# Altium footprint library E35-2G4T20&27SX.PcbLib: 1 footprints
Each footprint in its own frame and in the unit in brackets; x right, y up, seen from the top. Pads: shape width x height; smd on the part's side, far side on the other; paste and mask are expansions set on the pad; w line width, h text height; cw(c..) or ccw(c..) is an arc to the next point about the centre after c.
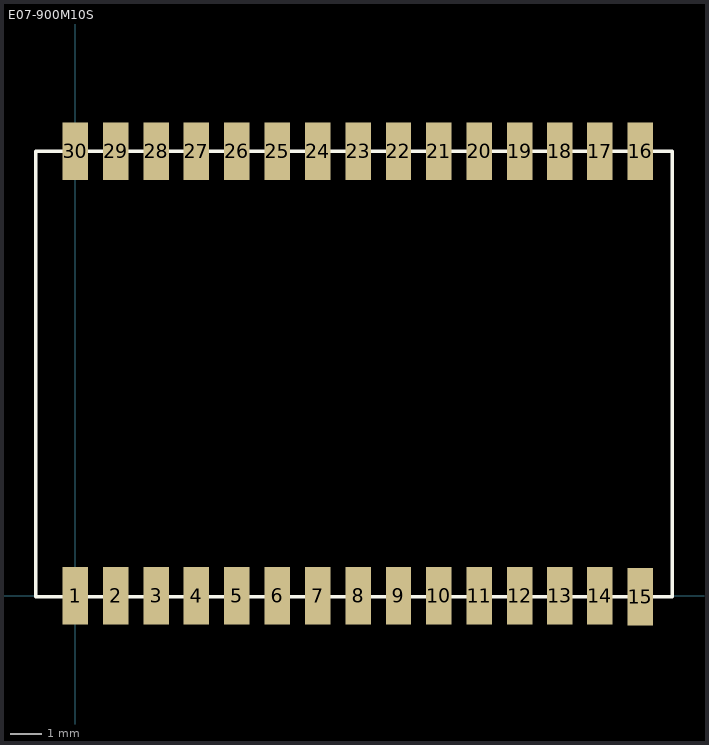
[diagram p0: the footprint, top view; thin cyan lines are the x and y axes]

## E07-900M10S [mm] "20mm*14mm*2.8mm-S"
pads (30):
  rect 0.8x1.8 smd: 1(0,0) 2(1.27,0) 3(2.54,0) 4(3.81,0) 5(5.08,0) 6(6.35,0) 7(7.62,0) 8(8.89,0) 9(10.16,0) 10(11.43,0) 11(12.7,0) 12(13.97,0) 13(15.222,0) 14(16.492,0) 15(17.762,-0.03) 16(17.762,13.97) 17(16.492,13.97) 18(15.222,13.97) 19(13.97,13.97) 20(12.7,13.97) 21(11.43,13.97) 22(10.16,13.97) 23(8.89,13.97) 24(7.62,13.97) 25(6.35,13.97) 26(5.08,13.97) 27(3.81,13.97) 28(2.54,13.97) 29(1.27,13.97) 30(0,13.97)
Top Overlay:
  lines w0.1: -1.238,-0.03 18.762,-0.03 18.762,13.97 -1.238,13.97 -1.238,-0.03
